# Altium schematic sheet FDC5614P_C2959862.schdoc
size 127 x 101 mm
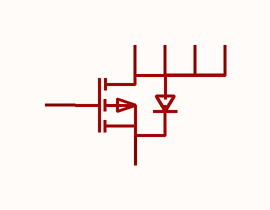
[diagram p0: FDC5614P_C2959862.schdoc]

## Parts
Q?  fdc5614p  [SOT-23-6_L2.9-W1.6-P0.95-LS2.8-BR]  (value not drawn)

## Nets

Not connected (* = marked no-connect by the designer): Q? 1(D) 2(D) 3(G) 4(S) 5(D) 6(D)

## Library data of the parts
Q? = fdc5614p: 数量:1个P沟道;漏源电压(Vdss):60V;连续漏极电流(Id):3A;导通电阻(RDS(on)):140mΩ@4.5V;耗散功率(Pd):1.92W;阈值电压(Vgs(th)):1.5V;; Manufacturer: TECH PUBLIC(台舟); Symbol: FDC5614P_C2959862; AddInBom: yes; ModelId: 18da8f6c14a34920b3e136b5c401a119; ModelName: SOT-23-6_L2.9-W1.6-H1.5-LS2.8-P0.95; ModelTransform: 110.73671,114.173,0,180,0,0,0.001,-0.003,0; Number: 1个P沟道; Drain to Source Voltage: 60V; Current - Continuous Drain(Id): 3A; Pd - Power Dissipation: 1.92W; Gate Threshold Voltage (Vgs(th)): 1.5V; Gate Charge(Qg): 17.7nC@10V; Input Capacitance(Ciss): 637pF; Reverse Transfer Capacitance (Crss@Vds): 53pF; Type: P沟道; Output Capacitance(Coss): 70pF; Vgs: ±20V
